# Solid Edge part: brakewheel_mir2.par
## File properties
Author: KULL
Template: Iso Metric Part.par
Last saved by: KULL
Revision: 2
Application: Solid Edge
Accuracy: 0,990
Username: KULL
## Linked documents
brakewheel.par
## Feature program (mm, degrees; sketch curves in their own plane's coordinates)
part copy "CopiedPart_1"
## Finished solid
Body 1: solid body, 544 faces, 1066 edges, 432 vertices.
  Faces by surface: torus 226, cylinder 204, blend 72, plane 42
  Edges by curve: circle 742, intersection 216, line 108
Bounding box of the edges (mm; curved faces can reach further): 52.000 x 5.000 x 52.000, from (-26, -123, -3) to (26, -118, 49).
Cylindrical faces by radius (mm): R0.2 x36, R0.7 x36, R0.8 x36, R0.9 x36, R4 x1, R10 x2, R14.7173 x18, R15 x2, R17 x18, R26 x1, R28.4 x18
Toroidal faces (ring radius, tube radius in mm): R0.8 r0.1 x36, R0.9 r0.1 x36, R1 r0.1 x36, R9.8 r0.2 x2, R10.2 r0.2 x2, R14.8 r0.2 x2, R15.1173 r0.4 x36, R15.2 r0.2 x2, R25.8 r0.2 x38, R28 r0.4 x36
Planar faces by outward normal: +y 21, -y 21
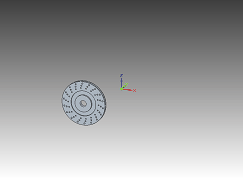
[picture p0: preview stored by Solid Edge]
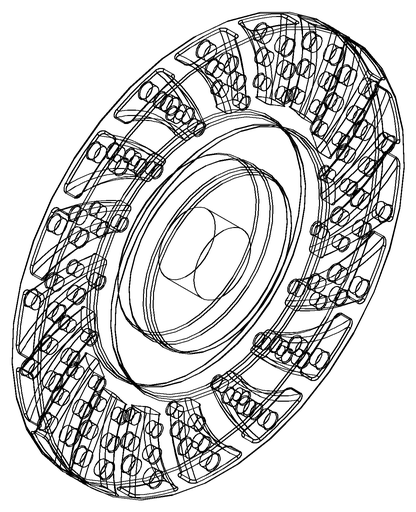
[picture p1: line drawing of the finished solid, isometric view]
